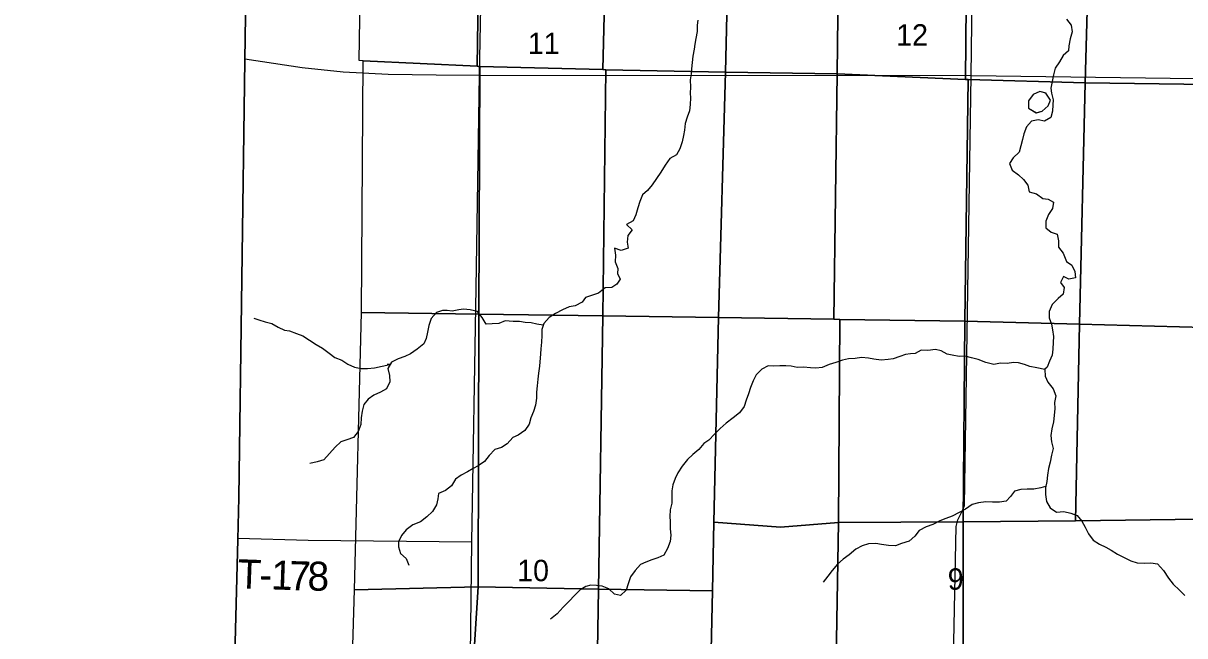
# Model space of a CAD drawing. Extents: x 1985906 to 2277390, y 930619 to 1324581.
# Drawn here: x 2056611 to 2068594, y 1097221 to 1103543 of the extents above; entities that cross this region are included whole.
import ezdxf

# ---------------------------------------------------------------- set-up
doc = ezdxf.new("R2010")
doc.units = 0
for name, color, linetype in [('GM_X_Adjacent_County', 7, 'Continuous'), ('GM_X_County', 7, 'Continuous'), ('GM_X_County_Road', 7, 'Continuous'), ('GM_X_Minor_Lake', 7, 'Continuous'), ('GM_X_Minor_River', 7, 'Continuous'), ('GM_X_Section', 7, 'Continuous'), ('GM_X_Section_Text', 7, 'Continuous'), ('GM_X_Township', 7, 'Continuous'), ('GM_X_Township_Road', 7, 'Continuous'), ('GM_X_Township_Road_Text', 7, 'Continuous'), ('GM_X_US_Route', 7, 'Continuous')]:
    doc.layers.add(name, color=color, linetype=linetype)

msp = doc.modelspace()

# ---------------------------------------------------------------- linework, layer by layer
at = {"layer": 'GM_X_Adjacent_County'}
msp.add_lwpolyline([(2040306, 1116370), (2045570, 1116279), (2050782, 1116223), (2056317, 1116164), (2059092, 1116134), (2059062, 1114191), (2059054, 1113649), (2058978, 1108653), (2058897, 1103161), (2058836, 1098648), (2058825, 1098215), (2058713, 1093964), (2058689, 1092990), (2058670, 1092146), (2058664, 1090110), (2061153, 1090093), (2061474, 1090093), (2065482, 1090095), (2066117, 1090095), (2068677, 1090072)], dxfattribs=at)
at = {"layer": 'GM_X_County'}
msp.add_lwpolyline([(2059186, 1123686), (2059120, 1118390), (2059092, 1116134), (2059062, 1114191), (2059054, 1113649), (2058978, 1108653), (2058897, 1103161), (2058836, 1098648), (2058825, 1098215), (2058713, 1093964), (2058689, 1092990), (2058670, 1092146), (2058664, 1090110), (2061153, 1090093), (2061474, 1090093), (2065482, 1090095), (2066117, 1090095), (2068677, 1090072)], dxfattribs=at)
at = {"layer": 'GM_X_County_Road'}
for points in [[(2061319, 1103007), (2061330, 1103710), (2061404, 1108657), (2061420, 1109886), (2061440, 1110984), (2061465, 1112120), (2061491, 1113601), (2061543, 1115775), (2061547, 1116080), (2061552, 1116120), (2061554, 1116131)], [(2061207, 1095559), (2061240, 1098191), (2061284, 1100813), (2061319, 1103007)]]:
    msp.add_lwpolyline(points, dxfattribs=at)
at = {"layer": 'GM_X_Minor_Lake'}
for points in [[(2067161, 1102821), (2067097, 1102837), (2067029, 1102808), (2066982, 1102741), (2066983, 1102668), (2067063, 1102619)], [(2067165, 1102820), (2067097, 1102837), (2067029, 1102808), (2066982, 1102741), (2066983, 1102668), (2067061, 1102620)], [(2067058, 1102617), (2067124, 1102636), (2067183, 1102690), (2067208, 1102750), (2067161, 1102820)], [(2067063, 1102619), (2067124, 1102636), (2067183, 1102690), (2067208, 1102750), (2067161, 1102821)]]:
    msp.add_lwpolyline(points, dxfattribs=at)
at = {"layer": 'GM_X_Minor_River'}
for points in [[(2063571, 1103576), (2063565, 1103525), (2063564, 1103457), (2063549, 1103386), (2063540, 1103326), (2063531, 1103274), (2063518, 1103205), (2063513, 1103137), (2063504, 1103072), (2063503, 1103022), (2063492, 1102958), (2063493, 1102885), (2063492, 1102823), (2063493, 1102773), (2063490, 1102703), (2063485, 1102638), (2063460, 1102574), (2063439, 1102507), (2063432, 1102441), (2063423, 1102384), (2063410, 1102320), (2063385, 1102247), (2063350, 1102184), (2063282, 1102147), (2063233, 1102078), (2063188, 1102007), (2063145, 1101940), (2063100, 1101877), (2063052, 1101816), (2063001, 1101771), (2062972, 1101703), (2062953, 1101638), (2062932, 1101567), (2062903, 1101505), (2062835, 1101465), (2062892, 1101410), (2062847, 1101353), (2062842, 1101283), (2062851, 1101223), (2062779, 1101197), (2062709, 1101220), (2062720, 1101150), (2062717, 1101082), (2062746, 1101012), (2062743, 1100960), (2062768, 1100902), (2062736, 1100851), (2062683, 1100814), (2062613, 1100813), (2062545, 1100758), (2062475, 1100733), (2062412, 1100714), (2062378, 1100663), (2062305, 1100626), (2062243, 1100615), (2062173, 1100584), (2062101, 1100547), (2062036, 1100507), (2061980, 1100444), (2061961, 1100382), (2061962, 1100319), (2061959, 1100251), (2061950, 1100183), (2061947, 1100132), (2061937, 1100004), (2061928, 1099931), (2061919, 1099869), (2061914, 1099800), (2061907, 1099734), (2061906, 1099672), (2061895, 1099601), (2061876, 1099535), (2061849, 1099470), (2061830, 1099406), (2061787, 1099339), (2061718, 1099291), (2061662, 1099268), (2061605, 1099203), (2061545, 1099164), (2061475, 1099145), (2061416, 1099082), (2061369, 1099021)], [(2067372, 1103586), (2067421, 1103523), (2067432, 1103455), (2067411, 1103382), (2067398, 1103309), (2067393, 1103259), (2067338, 1103210), (2067302, 1103145), (2067257, 1103078), (2067240, 1103010), (2067227, 1102941), (2067212, 1102873), (2067219, 1102823), (2067236, 1102753), (2067233, 1102702), (2067230, 1102634), (2067211, 1102569), (2067148, 1102532), (2067081, 1102545), (2067013, 1102534), (2066960, 1102473), (2066935, 1102403), (2066920, 1102342), (2066903, 1102278), (2066884, 1102213), (2066824, 1102154), (2066787, 1102095), (2066814, 1102027), (2066879, 1101980), (2066930, 1101930), (2066973, 1101873), (2066990, 1101803), (2067063, 1101782), (2067130, 1101733), (2067184, 1101727), (2067241, 1101696), (2067230, 1101630), (2067189, 1101569), (2067160, 1101500), (2067159, 1101432), (2067216, 1101388), (2067278, 1101367), (2067291, 1101299), (2067292, 1101231), (2067339, 1101171), (2067373, 1101083), (2067429, 1101046), (2067461, 1100982), (2067468, 1100916), (2067398, 1100903), (2067341, 1100930), (2067312, 1100868), (2067351, 1100814), (2067340, 1100747), (2067286, 1100702), (2067225, 1100639), (2067196, 1100568), (2067195, 1100502), (2067218, 1100436), (2067229, 1100380), (2067238, 1100310), (2067237, 1100250), (2067234, 1100179), (2067225, 1100117), (2067198, 1100056), (2067175, 1099992), (2067148, 1099968)], [(2061975, 1100428), (2061910, 1100437), (2061852, 1100452), (2061788, 1100455), (2061731, 1100463), (2061665, 1100464), (2061583, 1100470), (2061517, 1100445), (2061449, 1100440), (2061387, 1100437), (2061344, 1100505), (2061296, 1100569), (2061222, 1100584), (2061154, 1100591), (2061104, 1100586), (2061036, 1100571), (2060985, 1100578), (2060935, 1100577), (2060875, 1100556), (2060818, 1100495), (2060795, 1100425), (2060782, 1100356), (2060769, 1100290), (2060742, 1100233), (2060675, 1100180), (2060607, 1100132), (2060547, 1100103), (2060478, 1100080), (2060410, 1100045), (2060373, 1099978), (2060388, 1099908), (2060393, 1099842), (2060360, 1099771), (2060298, 1099734), (2060229, 1099705), (2060169, 1099664), (2060126, 1099607), (2060107, 1099540), (2060098, 1099470), (2060093, 1099402), (2060066, 1099331), (2060019, 1099268), (2059949, 1099243), (2059887, 1099222), (2059830, 1099167), (2059769, 1099103), (2059713, 1099036), (2059642, 1099015), (2059568, 1098998)], [(2058991, 1100498), (2059041, 1100483), (2059108, 1100461), (2059174, 1100444), (2059241, 1100405), (2059307, 1100376), (2059358, 1100367), (2059430, 1100342), (2059497, 1100317), (2059564, 1100271), (2059633, 1100228), (2059698, 1100189), (2059767, 1100138), (2059827, 1100093), (2059896, 1100064), (2059961, 1100024), (2060030, 1099993), (2060098, 1099980), (2060164, 1099981), (2060234, 1099988), (2060393, 1100022), (2060364, 1100022)], [(2067150, 1099968), (2067067, 1099986), (2066994, 1099999), (2066940, 1100020), (2066877, 1100037), (2066827, 1100043), (2066763, 1100032), (2066693, 1100035), (2066625, 1100020), (2066540, 1100040), (2066464, 1100071), (2066393, 1100090), (2066329, 1100106), (2066265, 1100105), (2066194, 1100116), (2066144, 1100129), (2066081, 1100162), (2066021, 1100175), (2065943, 1100166), (2065874, 1100169), (2065813, 1100136), (2065763, 1100131), (2065711, 1100124), (2065655, 1100104), (2065585, 1100080), (2065533, 1100072), (2065461, 1100066), (2065386, 1100075), (2065330, 1100085), (2065258, 1100092), (2065192, 1100083), (2065124, 1100080), (2065062, 1100067), (2064994, 1100043), (2064926, 1100022), (2064854, 1099989), (2064786, 1099984), (2064732, 1099985), (2064659, 1099994), (2064595, 1099991), (2064533, 1100002), (2064479, 1100006), (2064415, 1100007), (2064352, 1100002), (2064296, 1100007), (2064231, 1099972), (2064171, 1099915), (2064140, 1099852), (2064113, 1099785), (2064094, 1099717), (2064069, 1099652), (2064048, 1099587), (2064001, 1099522), (2063935, 1099471), (2063864, 1099416), (2063801, 1099359), (2063743, 1099302), (2063684, 1099240), (2063633, 1099207), (2063579, 1099144), (2063520, 1099093), (2063463, 1099040), (2063408, 1098971), (2063365, 1098904), (2063335, 1098843), (2063314, 1098779), (2063301, 1098718), (2063302, 1098658), (2063301, 1098590), (2063286, 1098521), (2063281, 1098451), (2063284, 1098399), (2063285, 1098326), (2063292, 1098260), (2063285, 1098194), (2063258, 1098123), (2063221, 1098054), (2063156, 1098025), (2063096, 1098006), (2063034, 1097979), (2062978, 1097956), (2062923, 1097893), (2062874, 1097830), (2062853, 1097756), (2062832, 1097691), (2062774, 1097636), (2062710, 1097651), (2062653, 1097706), (2062582, 1097733), (2062524, 1097739), (2062468, 1097744), (2062416, 1097729), (2062358, 1097696), (2062299, 1097637), (2062244, 1097578), (2062181, 1097516), (2062119, 1097447), (2062050, 1097394)], [(2067149, 1099969), (2067152, 1099899), (2067181, 1099839), (2067237, 1099770), (2067264, 1099698), (2067249, 1099629), (2067254, 1099565), (2067247, 1099495), (2067240, 1099428), (2067221, 1099356), (2067212, 1099287), (2067219, 1099223), (2067236, 1099153), (2067219, 1099084), (2067204, 1099014), (2067187, 1098947), (2067178, 1098879), (2067169, 1098812), (2067156, 1098748), (2067157, 1098678), (2067167, 1098607), (2067206, 1098542), (2067271, 1098495), (2067345, 1098504), (2067419, 1098487), (2067484, 1098464), (2067531, 1098404), (2067566, 1098342), (2067601, 1098274), (2067648, 1098209), (2067713, 1098168), (2067780, 1098135), (2067834, 1098105), (2067899, 1098064), (2067974, 1098025), (2068037, 1097996), (2068103, 1097973), (2068175, 1097972), (2068244, 1097975), (2068314, 1097962), (2068373, 1097894), (2068425, 1097817), (2068474, 1097753), (2068541, 1097692), (2068596, 1097637)], [(2061369, 1099021), (2061303, 1098976), (2061251, 1098949), (2061194, 1098914), (2061130, 1098877), (2061071, 1098836), (2061030, 1098767), (2060966, 1098722), (2060896, 1098688), (2060887, 1098636), (2060874, 1098572), (2060833, 1098505), (2060776, 1098450), (2060710, 1098396), (2060631, 1098365), (2060561, 1098316), (2060512, 1098255), (2060481, 1098190), (2060482, 1098140), (2060503, 1098070), (2060562, 1098017), (2060589, 1097949)], [(2067158, 1098760), (2067110, 1098749), (2067038, 1098734), (2066968, 1098735), (2066904, 1098732), (2066836, 1098713), (2066797, 1098660), (2066751, 1098609), (2066681, 1098600), (2066611, 1098599), (2066541, 1098602), (2066467, 1098593), (2066399, 1098576), (2066331, 1098527), (2066266, 1098492), (2066194, 1098456), (2066128, 1098431), (2066066, 1098408), (2065995, 1098369), (2065927, 1098344), (2065855, 1098307), (2065808, 1098250), (2065749, 1098197), (2065673, 1098175), (2065609, 1098150), (2065537, 1098151), (2065466, 1098162), (2065406, 1098173), (2065332, 1098170), (2065264, 1098149), (2065200, 1098114), (2065131, 1098057), (2065069, 1098012), (2065010, 1097961), (2064955, 1097895), (2064912, 1097837), (2064863, 1097774)]]:
    msp.add_lwpolyline(points, dxfattribs=at)
at = {"layer": 'GM_X_Section'}
for points in [[(2060119, 1105743), (2061331, 1105732), (2061293, 1103099), (2060117, 1103156), (2060078, 1103157)], [(2061331, 1105732), (2062656, 1105720), (2062590, 1103064), (2061322, 1103098), (2061308, 1103098), (2061293, 1103099)], [(2062656, 1105720), (2063919, 1105705), (2063856, 1103039), (2062621, 1103063), (2062590, 1103064)], [(2063919, 1105705), (2064850, 1105693), (2065040, 1105691), (2065008, 1103021), (2063856, 1103039)], [(2065040, 1105691), (2066357, 1105674), (2066333, 1102963), (2065008, 1103021)], [(2066357, 1105674), (2067642, 1105659), (2067566, 1102928), (2066358, 1102963), (2066333, 1102963)], [(2067642, 1105659), (2068912, 1105644), (2068837, 1102912), (2067566, 1102928)], [(2060117, 1103156), (2061293, 1103099), (2061308, 1103098), (2061322, 1103098), (2061312, 1100542), (2060100, 1100559)], [(2061322, 1103098), (2062590, 1103064), (2062621, 1103063), (2062590, 1100523), (2061312, 1100542)], [(2062621, 1103063), (2063856, 1103039), (2063783, 1100506), (2062590, 1100523)], [(2063856, 1103039), (2065008, 1103021), (2064973, 1100488), (2063783, 1100506)], [(2065008, 1103021), (2066333, 1102963), (2066358, 1102963), (2066325, 1100468), (2065036, 1100487), (2064973, 1100488)], [(2066358, 1102963), (2067566, 1102928), (2067508, 1100437), (2066325, 1100468)], [(2067566, 1102928), (2068837, 1102912), (2068798, 1100403), (2067508, 1100437)], [(2061312, 1100542), (2061304, 1097726), (2060028, 1097696), (2060100, 1100559)], [(2061312, 1100542), (2062590, 1100523), (2062544, 1097703), (2061304, 1097726)], [(2062590, 1100523), (2063783, 1100506), (2063737, 1098394), (2063721, 1097684), (2062544, 1097703)], [(2063783, 1100506), (2064973, 1100488), (2065036, 1100487), (2065022, 1098390), (2064424, 1098342), (2063737, 1098394)], [(2065036, 1100487), (2066325, 1100468), (2066307, 1098396), (2065022, 1098390)], [(2066325, 1100468), (2067508, 1100437), (2067466, 1098406), (2066307, 1098396)], [(2068798, 1100403), (2068780, 1099638), (2068751, 1098426), (2067466, 1098406), (2067508, 1100437)], [(2063737, 1098394), (2064424, 1098342), (2065022, 1098390), (2064969, 1095352), (2063671, 1095389), (2063721, 1097684)], [(2065022, 1098390), (2066307, 1098396), (2066304, 1095314), (2064969, 1095352)], [(2067466, 1098406), (2068751, 1098426), (2068726, 1097357), (2068677, 1095246), (2066304, 1095314), (2066307, 1098396)], [(2060028, 1097696), (2061304, 1097726), (2061157, 1095386), (2059960, 1095385)], [(2061304, 1097726), (2062544, 1097703), (2062507, 1095388), (2062383, 1095388), (2061157, 1095386)], [(2062544, 1097703), (2063721, 1097684), (2063671, 1095389), (2062507, 1095388)]]:
    msp.add_lwpolyline(points, close=True, dxfattribs=at)
at = {"layer": 'GM_X_Township'}
msp.add_lwpolyline([(2068677, 1090072), (2066117, 1090095), (2065482, 1090095), (2061474, 1090093), (2061153, 1090093), (2058664, 1090110), (2058670, 1092146), (2058689, 1092990), (2058713, 1093964), (2058825, 1098215), (2058836, 1098648), (2058897, 1103161), (2058978, 1108653), (2059054, 1113649), (2059062, 1114191), (2059092, 1116134), (2061552, 1116120), (2063356, 1116100), (2066831, 1116083), (2071945, 1116057)], dxfattribs=at)
at = {"layer": 'GM_X_Township_Road'}
for points in [[(2066390, 1103003), (2066464, 1108600), (2066469, 1108959), (2066460, 1109075), (2066446, 1109180), (2066449, 1109264), (2066459, 1109385), (2066490, 1113568), (2066509, 1115603), (2066519, 1115731), (2066565, 1115832), (2066653, 1115917), (2066785, 1116015), (2066831, 1116083), (2066846, 1116134), (2066847, 1116135)], [(2066147, 1094212), (2066178, 1095453), (2066234, 1098350), (2066252, 1098416), (2066305, 1098521), (2066323, 1098567), (2066390, 1103003)], [(2058826, 1098228), (2059551, 1098207), (2061240, 1098191)]]:
    msp.add_lwpolyline(points, dxfattribs=at)
at = {"layer": 'GM_X_US_Route'}
msp.add_lwpolyline([(2058897, 1103176), (2059489, 1103085), (2059910, 1103042), (2060374, 1103018), (2060871, 1103009), (2061319, 1103007), (2066390, 1103003), (2070243, 1102953)], dxfattribs=at)

# ---------------------------------------------------------------- texts
at = {"layer": 'GM_X_Section_Text'}
for s, p in [('12', (2065616, 1103312)), ('11', (2061816, 1103225)), ('10', (2061706, 1097784)), ('9', (2066148, 1097696))]:
    msp.add_text(s, height=221, rotation=0, dxfattribs=at).set_placement(p)
at = {"layer": 'GM_X_Township_Road_Text'}
for s, rotation, p in [('T', 357.891, (2058816, 1097712)), ('1', 358.0206, (2059164, 1097700)), ('7', 358.3101, (2059351, 1097693)), ('8', 359.3794, (2059542, 1097687)), ('-', 357.9239, (2059041, 1097704))]:
    msp.add_text(s, height=300, rotation=rotation, dxfattribs=at).set_placement(p)

doc.saveas('drawing.dxf')
